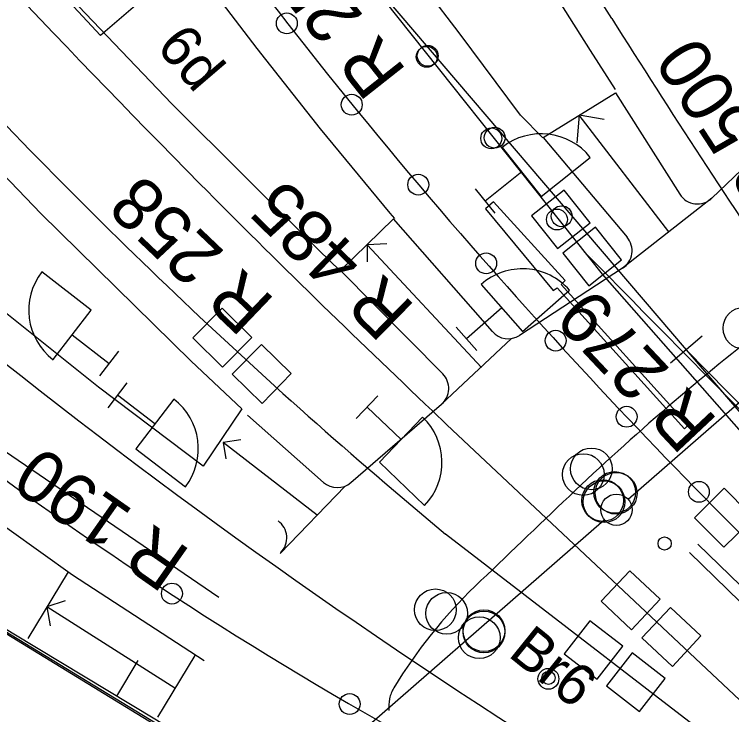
# Model space of a CAD drawing. Extents: x 1596643 to 1597288, y 13057194 to 13057957.
# Drawn here: x 1596850.68 to 1596885.06, y 13057472.66 to 13057506.23 of the extents above; entities that cross this region are included whole.
import ezdxf

# ---------------------------------------------------------------- set-up
doc = ezdxf.new("R2010")
doc.units = 0
for name, color, linetype in [('A Spårgeometri T', 7, 'Continuous'), ('A spårmitt L', 7, 'Continuous'), ('B kabelbrunn mindre än 150 cm NK P', 7, 'Continuous'), ('B kabelränna 300-400 mm NK L', 7, 'Continuous'), ('B kabelränna 400-500 mm NK L', 7, 'Continuous'), ('B kabelränna större än 500 mm NK L', 7, 'Continuous'), ('B växel linjevikt 0 L', 7, 'Continuous'), ('BAS Level 15', 7, 'Continuous'), ('BAS Level 18', 7, 'Continuous'), ('BAS Level 19', 7, 'Continuous'), ('BAS Level 29', 7, 'Continuous'), ('BAS Level 37', 7, 'Continuous'), ('BAS stödmur fot L', 7, 'Continuous'), ('BAS stödmur krön L', 7, 'Continuous'), ('D Plattform L', 7, 'Continuous'), ('D plattform tak L', 7, 'Continuous'), ('E ktlbrygga L', 7, 'Continuous'), ('E ktlbrygga T', 7, 'Continuous'), ('E ktlstolpe normal centrum P', 7, 'Continuous'), ('E ktlstolpe T', 7, 'Continuous'), ('F balis P', 7, 'Continuous'), ('F dvärgsignal fristående P', 7, 'Continuous'), ('F signal fristående P', 7, 'Continuous'), ('F vägskyddsanordning stolpe driv P', 7, 'Continuous')]:
    doc.layers.add(name, color=color, linetype=linetype)

msp = doc.modelspace()

# ---------------------------------------------------------------- linework, layer by layer
at = {"layer": 'A spårmitt L'}
msp.add_line((1596879.311, 13057506.034), (1596843.07, 13057563.495), dxfattribs=at)
for points in [[(1596861.603, 13057516.009), (1596866.442, 13057509.391), (1596878.849, 13057493.781), (1596895.097, 13057475.302), (1596900.34, 13057469.714), (1596931.231, 13057437.468), (1596933.8, 13057434.835)], [(1596870.725, 13057487.218), (1596871.41, 13057486.548), (1596888.081, 13057470.874), (1596909.882, 13057451.74)], [(1596901.218, 13057459.344), (1596886.823, 13057469.398), (1596871.343, 13057481.319)]]:
    msp.add_lwpolyline(points, dxfattribs=at)
for centre, radius, start, end in [((1597214.65, 13057850.135), 500, 218.04271, 224.75231), ((1596499.999, 13057297.54), 450, 26.52378, 31.49284), ((1597037.43, 13057725.326), 301.08, 223.02589, 237.32659), ((1597060.917, 13057659.535), 250, 215.49853, 221.11206), ((1597302.22, 13057772.77), 500, 212.24025, 214.05857), ((1597036.217, 13057679.675), 257.932, 222.55623, 230.26648), ((1596962.077, 13057637.523), 190, 226.32199, 243.66622), ((1597204.501, 13057840.074), 485.71, 224.75231, 226.59166), ((1597083.054, 13057678.855), 279.382, 221.11205, 225.426)]:
    msp.add_arc(centre, radius, start, end, dxfattribs=at)
msp.add_spline([(1596921.486, 13057453.819), (1596905.281, 13057468.17), (1596896.354, 13057476.52), (1596877.996, 13057494.854)], degree=3, dxfattribs=at)
at = {"layer": 'B kabelbrunn mindre än 150 cm NK P'}
msp.add_circle((1596876.274, 13057474.378), 0.5, dxfattribs=at)
msp.add_circle((1596876.274, 13057474.378), 0.5, dxfattribs=at)
at = {"layer": 'B kabelränna 300-400 mm NK L'}
msp.add_lwpolyline([(1596876.702, 13057493.127), (1596882.793, 13057486.355), (1596882.972, 13057486.535), (1596876.885, 13057493.277)], dxfattribs=at)
at = {"layer": 'B kabelränna 400-500 mm NK L'}
msp.add_lwpolyline([(1596883.038, 13057480.441), (1596889.091, 13057474.53), (1596902.563, 13057461.987), (1596910.703, 13057454.289), (1596911.093, 13057454.69), (1596913.886, 13057457.525), (1596927.553, 13057443.815), (1596936.728, 13057434.552), (1596947.807, 13057423.165), (1596958.841, 13057412.087), (1596959.17, 13057412.506), (1596945.763, 13057426.086), (1596935.532, 13057436.607), (1596925.003, 13057447.233), (1596913.927, 13057458.386), (1596910.643, 13057455.068), (1596902.92, 13057462.372), (1596891.14, 13057473.364), (1596883.436, 13057480.826)], dxfattribs=at)
at = {"layer": 'B kabelränna större än 500 mm NK L'}
for points in [[(1596876.885, 13057493.277), (1596877.082, 13057493.481), (1596873.644, 13057497.252), (1596873.254, 13057496.909)], [(1596873.254, 13057496.909), (1596876.501, 13057493), (1596876.702, 13057493.127)]]:
    msp.add_lwpolyline(points, dxfattribs=at)
at = {"layer": 'B växel linjevikt 0 L'}
for p, q in [((1596866.447, 13057509.394), (1596882.884, 13057490.154)), ((1596866.447, 13057509.394), (1596882.884, 13057490.154)), ((1596883.645, 13057490.804), (1596882.124, 13057489.505)), ((1596883.645, 13057490.804), (1596882.124, 13057489.505)), ((1596882.884, 13057490.154), (1596901.664, 13057468.173)), ((1596882.884, 13057490.154), (1596903.084, 13057469.471)), ((1596882.884, 13057490.154), (1596901.664, 13057468.173)), ((1596882.884, 13057490.154), (1596903.084, 13057469.471))]:
    msp.add_line(p, q, dxfattribs=at)
at = {"layer": 'BAS Level 15'}
for centre in [(1596863.738, 13057505.801), (1596863.738, 13057505.801), (1596870.444, 13057504.197), (1596870.444, 13057504.197), (1596870.492, 13057504.246), (1596870.492, 13057504.246), (1596866.849, 13057501.903), (1596866.849, 13057501.903), (1596873.699, 13057500.32), (1596873.699, 13057500.32), (1596873.536, 13057500.288), (1596873.536, 13057500.288), (1596870.036, 13057498.068), (1596870.036, 13057498.068), (1596876.91, 13057496.554), (1596876.91, 13057496.554), (1596876.682, 13057496.401), (1596876.682, 13057496.401), (1596873.29, 13057494.296), (1596873.29, 13057494.296), (1596876.623, 13057490.59), (1596876.623, 13057490.59), (1596880.023, 13057486.943), (1596880.023, 13057486.943), (1596883.487, 13057483.341), (1596883.487, 13057483.341), (1596858.232, 13057478.463), (1596858.232, 13057478.463), (1596866.75, 13057473.169), (1596866.75, 13057473.169)]:
    msp.add_circle(centre, 0.5, dxfattribs=at)
at = {"layer": 'BAS Level 18'}
msp.add_line((1596855.588, 13057473.538), (1596856.621, 13057475.251), dxfattribs=at)
msp.add_line((1596855.588, 13057473.538), (1596856.621, 13057475.251), dxfattribs=at)
at = {"layer": 'BAS Level 19'}
msp.add_lwpolyline([(1596860.482, 13057478.28), (1596850.2, 13057485.288), (1596843.794, 13057490.442), (1596834.422, 13057498.747), (1596829.686, 13057503.602)], dxfattribs=at)
at = {"layer": 'BAS Level 29'}
for centre in [(1596881.845, 13057480.863), (1596881.845, 13057480.863), (1596876.278, 13057474.425), (1596876.278, 13057474.425)]:
    msp.add_circle(centre, 0.318, dxfattribs=at)
at = {"layer": 'BAS Level 37'}
msp.add_lwpolyline([(1596872.455, 13057463.088), (1596840.526, 13057482.557)], dxfattribs=at)
at = {"layer": 'BAS stödmur fot L'}
msp.add_lwpolyline([(1596801.38, 13057521.802), (1596807.902, 13057515.293), (1596815.586, 13057507.536), (1596822.317, 13057500.788), (1596829.481, 13057493.571), (1596836.802, 13057486.17), (1596840.401, 13057482.599), (1596850.573, 13057476.382), (1596857.34, 13057472.24), (1596864.058, 13057468.19)], dxfattribs=at)
at = {"layer": 'BAS stödmur krön L'}
msp.add_lwpolyline([(1596864.123, 13057468.328), (1596857.409, 13057472.44), (1596850.653, 13057476.515), (1596840.554, 13057482.67), (1596836.91, 13057486.331), (1596829.604, 13057493.672), (1596822.422, 13057500.909), (1596815.38, 13057507.962), (1596808.004, 13057515.412), (1596801.503, 13057521.945)], dxfattribs=at)
at = {"layer": 'D Plattform L'}
for p, q in [((1596876.02, 13057500.33), (1596879.488, 13057502.476)), ((1596879.488, 13057502.476), (1596882.573, 13057497.608)), ((1596884.112, 13057497.423), (1596889.337, 13057502.456)), ((1596877.754, 13057501.403), (1596877.634, 13057500.077)), ((1596882.053, 13057495.807), (1596877.754, 13057501.403)), ((1596878.954, 13057501.196), (1596877.754, 13057501.403)), ((1596876.02, 13057500.33), (1596880.05, 13057495.546)), ((1596884.112, 13057497.423), (1596879.831, 13057494.064)), ((1596866.314, 13057493.956), (1596868.849, 13057496.423)), ((1596873.59, 13057491.024), (1596868.849, 13057496.423)), ((1596868.535, 13057495.226), (1596867.582, 13057495.19)), ((1596873.061, 13057489.307), (1596867.582, 13057495.19)), ((1596867.582, 13057495.19), (1596867.588, 13057494.365)), ((1596871.21, 13057489.001), (1596866.314, 13057493.956)), ((1596879.831, 13057494.064), (1596874.887, 13057490.845)), ((1596874.505, 13057490.697), (1596871.152, 13057487.542)), ((1596866.808, 13057483.787), (1596871.152, 13057487.542)), ((1596861.861, 13057487.024), (1596865.49, 13057483.797)), ((1596861.531, 13057485.84), (1596860.691, 13057485.709)), ((1596865.187, 13057482.222), (1596860.691, 13057485.709)), ((1596860.691, 13057485.709), (1596860.814, 13057484.921)), ((1596866.533, 13057483.618), (1596863.425, 13057480.38)), ((1596853.26, 13057479.507), (1596851.324, 13057476.307)), ((1596853.12, 13057478.121), (1596852.244, 13057477.828)), ((1596858.373, 13057473.925), (1596852.244, 13057477.828)), ((1596852.244, 13057477.828), (1596852.4, 13057476.922)), ((1596859.324, 13057475.498), (1596857.539, 13057472.547))]:
    msp.add_line(p, q, dxfattribs=at)
for points in [[(1596864.26, 13057526.7), (1596867.582, 13057521.437), (1596872.945, 13057512.951), (1596878.283, 13057504.508), (1596879.469, 13057502.624)], [(1596876.006, 13057500.307), (1596874.935, 13057501.4), (1596871.998, 13057505.344), (1596868.969, 13057509.328), (1596865.966, 13057513.26), (1596862.965, 13057517.282), (1596858.71, 13057523.059)], [(1596850.982, 13057520.161), (1596853.321, 13057516.805), (1596856.235, 13057512.713), (1596859.19, 13057508.682), (1596862.296, 13057504.59), (1596865.339, 13057500.75), (1596868.682, 13057496.703), (1596868.901, 13057496.442)], [(1596866.296, 13057493.938), (1596865.277, 13057494.926), (1596858.22, 13057501.943), (1596851.337, 13057509.173), (1596845.311, 13057515.752)], [(1596814.722, 13057513.813), (1596818.79, 13057509.576), (1596821.683, 13057506.586), (1596825.889, 13057502.375), (1596833.23, 13057495.42), (1596840.897, 13057488.807), (1596848.901, 13057482.619), (1596853.46, 13057479.369), (1596859.783, 13057475.256)], [(1596836.591, 13057513.337), (1596838.216, 13057511.491), (1596844.973, 13057503.951), (1596851.951, 13057496.684), (1596859.146, 13057489.613), (1596861.58, 13057487.322)], [(1596861.58, 13057487.322), (1596859.729, 13057484.577), (1596854.718, 13057488.355), (1596846.952, 13057494.556), (1596839.346, 13057501.034), (1596832, 13057507.739), (1596831.27, 13057508.417)]]:
    msp.add_lwpolyline(points, dxfattribs=at)
for centre, radius, start, end in [((1596883.418, 13057498.143), 1, 212.3631, 313.9223), ((1596879.285, 13057494.902), 1, 303.064, 40.1122), ((1596959.547, 13057397.271), 118.908, 127.62678, 130.70537), ((1596874.341, 13057491.683), 1, 221.2862, 303.064), ((1596870.498, 13057488.298), 1, 310.8437, 44.6557), ((1596964.441, 13057391.583), 126.412, 130.70539, 133.60119), ((1596866.154, 13057484.544), 1, 228.3484, 310.8356), ((1597604.836, 13056719.13), 1055.012, 133.601186, 133.939606), ((1596862.739, 13057481.135), 1, 315.2593, 54.4217), ((1596889.638, 13057461.302), 24.32, 133.9396, 148.6612), ((1596870.172, 13057473.156), 1.529, 148.6609, 170.014), ((1596871.099, 13057472.993), 2.47, 170.0147, 183.1848)]:
    msp.add_arc(centre, radius, start, end, dxfattribs=at)
at = {"layer": 'D plattform tak L'}
msp.add_lwpolyline([(1596791.643, 13057603.754), (1596794.543, 13057599.677), (1596800.292, 13057591.62), (1596806.147, 13057583.416), (1596811.988, 13057575.257), (1596817.843, 13057567.087), (1596823.598, 13057559.058), (1596826.007, 13057555.757), (1596826.02, 13057555.684), (1596829.426, 13057550.911), (1596835.25, 13057542.713), (1596840.981, 13057534.653), (1596846.813, 13057526.461), (1596852.619, 13057518.322), (1596859.283, 13057509.064), (1596854.815, 13057505.213), (1596851.39, 13057508.912), (1596844.685, 13057516.187), (1596838.116, 13057523.683), (1596831.752, 13057531.187), (1596825.407, 13057538.897), (1596819.262, 13057546.672), (1596816.697, 13057550.092), (1596826.02, 13057555.684)], dxfattribs=at)
at = {"layer": 'E ktlbrygga L'}
for points in [[(1596894.502, 13057495.528), (1596880.1, 13057482.978)], [(1596878.954, 13057481.979), (1596864.552, 13057469.43)]]:
    msp.add_lwpolyline(points, dxfattribs=at)
at = {"layer": 'E ktlstolpe normal centrum P'}
msp.add_circle((1596879.536, 13057482.485), 0.75, dxfattribs=at)
msp.add_circle((1596879.536, 13057482.485), 0.75, dxfattribs=at)
at = {"layer": 'F balis P'}
for p, q in [((1596877.033, 13057497.811), (1596875.467, 13057496.567)), ((1596877.033, 13057497.811), (1596875.467, 13057496.567)), ((1596878.277, 13057496.245), (1596877.033, 13057497.811)), ((1596878.277, 13057496.245), (1596877.033, 13057497.811)), ((1596875.467, 13057496.567), (1596876.711, 13057495.001)), ((1596875.467, 13057496.567), (1596876.711, 13057495.001)), ((1596876.872, 13057496.406), (1596876.872, 13057496.406)), ((1596876.872, 13057496.406), (1596876.872, 13057496.406)), ((1596876.711, 13057495.001), (1596878.277, 13057496.245)), ((1596876.711, 13057495.001), (1596878.277, 13057496.245)), ((1596878.532, 13057496.03), (1596876.966, 13057494.786)), ((1596878.532, 13057496.03), (1596876.966, 13057494.786)), ((1596879.776, 13057494.464), (1596878.532, 13057496.03)), ((1596879.776, 13057494.464), (1596878.532, 13057496.03)), ((1596876.966, 13057494.786), (1596878.21, 13057493.22)), ((1596876.966, 13057494.786), (1596878.21, 13057493.22)), ((1596878.371, 13057494.625), (1596878.371, 13057494.625)), ((1596878.371, 13057494.625), (1596878.371, 13057494.625)), ((1596878.21, 13057493.22), (1596879.776, 13057494.464)), ((1596878.21, 13057493.22), (1596879.776, 13057494.464)), ((1596860.632, 13057492.149), (1596859.229, 13057490.724)), ((1596860.632, 13057492.149), (1596859.229, 13057490.724)), ((1596862.057, 13057490.746), (1596860.632, 13057492.149)), ((1596862.057, 13057490.746), (1596860.632, 13057492.149)), ((1596859.229, 13057490.724), (1596860.654, 13057489.321)), ((1596859.229, 13057490.724), (1596860.654, 13057489.321)), ((1596860.643, 13057490.735), (1596860.643, 13057490.735)), ((1596860.643, 13057490.735), (1596860.643, 13057490.735)), ((1596860.654, 13057489.321), (1596862.057, 13057490.746)), ((1596860.654, 13057489.321), (1596862.057, 13057490.746)), ((1596862.517, 13057490.409), (1596861.12, 13057488.976)), ((1596862.517, 13057490.409), (1596861.12, 13057488.976)), ((1596863.95, 13057489.012), (1596862.517, 13057490.409)), ((1596863.95, 13057489.012), (1596862.517, 13057490.409)), ((1596861.12, 13057488.976), (1596862.553, 13057487.579)), ((1596861.12, 13057488.976), (1596862.553, 13057487.579)), ((1596862.535, 13057488.994), (1596862.535, 13057488.994)), ((1596862.535, 13057488.994), (1596862.535, 13057488.994)), ((1596862.553, 13057487.579), (1596863.95, 13057489.012)), ((1596862.553, 13057487.579), (1596863.95, 13057489.012)), ((1596884.696, 13057483.511), (1596883.276, 13057482.103)), ((1596884.696, 13057483.511), (1596883.276, 13057482.103)), ((1596886.104, 13057482.091), (1596884.696, 13057483.511)), ((1596886.104, 13057482.091), (1596884.696, 13057483.511)), ((1596883.276, 13057482.103), (1596884.684, 13057480.683)), ((1596883.276, 13057482.103), (1596884.684, 13057480.683)), ((1596884.684, 13057480.683), (1596886.104, 13057482.091)), ((1596884.684, 13057480.683), (1596886.104, 13057482.091)), ((1596884.69, 13057482.097), (1596884.69, 13057482.097)), ((1596884.69, 13057482.097), (1596884.69, 13057482.097)), ((1596880.171, 13057479.562), (1596878.801, 13057478.104)), ((1596880.171, 13057479.562), (1596878.801, 13057478.104)), ((1596881.629, 13057478.192), (1596880.171, 13057479.562)), ((1596881.629, 13057478.192), (1596880.171, 13057479.562)), ((1596880.215, 13057478.148), (1596880.215, 13057478.148)), ((1596880.215, 13057478.148), (1596880.215, 13057478.148)), ((1596880.259, 13057476.734), (1596881.629, 13057478.192)), ((1596880.259, 13057476.734), (1596881.629, 13057478.192)), ((1596878.801, 13057478.104), (1596880.259, 13057476.734)), ((1596878.801, 13057478.104), (1596880.259, 13057476.734)), ((1596882.127, 13057477.801), (1596880.757, 13057476.343)), ((1596882.127, 13057477.801), (1596880.757, 13057476.343)), ((1596883.585, 13057476.431), (1596882.127, 13057477.801)), ((1596883.585, 13057476.431), (1596882.127, 13057477.801)), ((1596878.255, 13057477.159), (1596877.035, 13057475.575)), ((1596878.255, 13057477.159), (1596877.035, 13057475.575)), ((1596879.839, 13057475.939), (1596878.255, 13057477.159)), ((1596879.839, 13057475.939), (1596878.255, 13057477.159)), ((1596882.215, 13057474.973), (1596883.585, 13057476.431)), ((1596882.215, 13057474.973), (1596883.585, 13057476.431)), ((1596880.757, 13057476.343), (1596882.215, 13057474.973)), ((1596880.757, 13057476.343), (1596882.215, 13057474.973)), ((1596882.171, 13057476.387), (1596882.171, 13057476.387)), ((1596882.171, 13057476.387), (1596882.171, 13057476.387)), ((1596878.437, 13057475.757), (1596878.437, 13057475.757)), ((1596878.437, 13057475.757), (1596878.437, 13057475.757)), ((1596878.619, 13057474.355), (1596879.839, 13057475.939)), ((1596878.619, 13057474.355), (1596879.839, 13057475.939)), ((1596877.035, 13057475.575), (1596878.619, 13057474.355)), ((1596877.035, 13057475.575), (1596878.619, 13057474.355)), ((1596880.281, 13057475.62), (1596879.061, 13057474.036)), ((1596880.281, 13057475.62), (1596879.061, 13057474.036)), ((1596881.865, 13057474.4), (1596880.281, 13057475.62)), ((1596881.865, 13057474.4), (1596880.281, 13057475.62)), ((1596880.645, 13057472.816), (1596881.865, 13057474.4)), ((1596880.645, 13057472.816), (1596881.865, 13057474.4)), ((1596879.061, 13057474.036), (1596880.645, 13057472.816)), ((1596879.061, 13057474.036), (1596880.645, 13057472.816)), ((1596880.463, 13057474.218), (1596880.463, 13057474.218)), ((1596880.463, 13057474.218), (1596880.463, 13057474.218))]:
    msp.add_line(p, q, dxfattribs=at)
at = {"layer": 'F dvärgsignal fristående P'}
for p, q in [((1596874.997, 13057498.683), (1596873.236, 13057497.283)), ((1596874.997, 13057498.683), (1596873.236, 13057497.283)), ((1596872.769, 13057497.87), (1596873.703, 13057496.696)), ((1596872.769, 13057497.87), (1596873.703, 13057496.696)), ((1596874.041, 13057492.162), (1596872.35, 13057490.677)), ((1596874.041, 13057492.162), (1596872.35, 13057490.677)), ((1596871.855, 13057491.241), (1596872.845, 13057490.113)), ((1596871.855, 13057491.241), (1596872.845, 13057490.113)), ((1596853.451, 13057490.866), (1596855.231, 13057489.49)), ((1596853.451, 13057490.866), (1596855.231, 13057489.49)), ((1596854.772, 13057488.897), (1596855.69, 13057490.083)), ((1596854.772, 13057488.897), (1596855.69, 13057490.083)), ((1596856.078, 13057488.564), (1596855.166, 13057487.374)), ((1596856.078, 13057488.564), (1596855.166, 13057487.374)), ((1596857.408, 13057486.601), (1596855.622, 13057487.969)), ((1596857.408, 13057486.601), (1596855.622, 13057487.969)), ((1596868.102, 13057487.941), (1596867.064, 13057486.857)), ((1596868.102, 13057487.941), (1596867.064, 13057486.857)), ((1596869.21, 13057485.844), (1596867.583, 13057487.399)), ((1596869.21, 13057485.844), (1596867.583, 13057487.399))]:
    msp.add_line(p, q, dxfattribs=at)
for points in [[(1596874.064, 13057499.857), (1596875.931, 13057497.509), (1596878.279, 13057499.375)], [(1596874.064, 13057499.857), (1596875.931, 13057497.509), (1596878.279, 13057499.375)], [(1596852.534, 13057489.679), (1596854.368, 13057492.052), (1596851.993, 13057493.887)], [(1596852.534, 13057489.679), (1596854.368, 13057492.052), (1596851.993, 13057493.887)], [(1596873.051, 13057493.289), (1596875.03, 13057491.035), (1596877.285, 13057493.014)], [(1596873.051, 13057493.289), (1596875.03, 13057491.035), (1596877.285, 13057493.014)], [(1596858.32, 13057487.792), (1596856.496, 13057485.41), (1596858.878, 13057483.586)], [(1596858.32, 13057487.792), (1596856.496, 13057485.41), (1596858.878, 13057483.586)], [(1596870.246, 13057486.929), (1596868.174, 13057484.76), (1596870.343, 13057482.688)], [(1596870.246, 13057486.929), (1596868.174, 13057484.76), (1596870.343, 13057482.688)]]:
    msp.add_lwpolyline(points, dxfattribs=at)
for centre, start, end in [((1596875.931, 13057497.509), 38.4782, 128.4782), ((1596875.931, 13057497.509), 38.4782, 128.4782), ((1596875.03, 13057491.034), 41.2872, 131.2872), ((1596875.03, 13057491.034), 41.2872, 131.2872), ((1596854.367, 13057492.052), 142.3114, 232.3114), ((1596854.367, 13057492.052), 142.3114, 232.3114), ((1596856.496, 13057485.41), 322.5488, 52.5488), ((1596856.496, 13057485.41), 322.5488, 52.5488), ((1596868.174, 13057484.76), 316.3088, 46.3088), ((1596868.174, 13057484.76), 316.3088, 46.3088)]:
    msp.add_arc(centre, 3, start, end, dxfattribs=at)
at = {"layer": 'F signal fristående P'}
for centre in [(1596885.645, 13057491.187), (1596885.645, 13057491.187), (1596878.336, 13057484.443), (1596878.336, 13057484.443), (1596877.944, 13057484.172), (1596877.944, 13057484.172), (1596879.453, 13057483.313), (1596879.453, 13057483.313), (1596878.876, 13057482.925), (1596878.876, 13057482.925), (1596870.859, 13057477.688), (1596870.859, 13057477.688), (1596871.399, 13057477.516), (1596871.399, 13057477.516), (1596873.185, 13057476.683), (1596873.185, 13057476.683)]:
    msp.add_circle(centre, 1, dxfattribs=at)
at = {"layer": 'F vägskyddsanordning stolpe driv P'}
for centre in [(1596879.521, 13057483.275), (1596879.521, 13057483.275), (1596878.942, 13057482.868), (1596878.942, 13057482.868), (1596873.184, 13057476.626), (1596873.184, 13057476.626), (1596872.959, 13057476.348), (1596872.959, 13057476.348)]:
    msp.add_circle(centre, 1, dxfattribs=at)

# ---------------------------------------------------------------- texts
at = {"layer": 'A Spårgeometri T'}
for s, height, rotation, p in [('R 250', 2.5, 128.313, (1596869.526, 13057503.512)), ('R 500', 2.499, 123.156, (1596888.271, 13057497.871)), ('R 258', 2.5, 136.377, (1596863.232, 13057492.51)), ('R 485', 2.499, 135.675, (1596869.953, 13057492.216)), ('R 279', 2.5, 133.272, (1596884.452, 13057486.754)), ('R 190', 2.5, 144.999, (1596859.199, 13057480.493))]:
    msp.add_text(s, height=height, rotation=rotation, dxfattribs=at).set_placement(p)
at = {"layer": 'E ktlbrygga T'}
msp.add_text('Br6', height=1.999, rotation=321.1082, dxfattribs=at).set_placement((1596874.285, 13057475.503))
at = {"layer": 'E ktlstolpe T'}
msp.add_text('6d', height=1.999, rotation=310.5574, dxfattribs=at).set_placement((1596857.431, 13057504.656))

doc.saveas('drawing.dxf')
